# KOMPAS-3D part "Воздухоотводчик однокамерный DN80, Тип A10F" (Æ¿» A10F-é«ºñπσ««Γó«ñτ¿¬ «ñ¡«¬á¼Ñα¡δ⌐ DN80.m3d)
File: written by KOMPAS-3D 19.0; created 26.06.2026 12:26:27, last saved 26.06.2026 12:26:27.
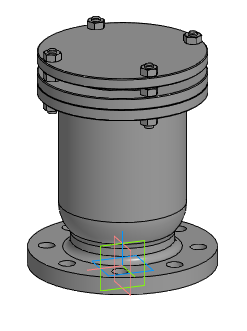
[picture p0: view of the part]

Document properties: Автор: Энергия; Полное имя файла: Z:\3.Личные\kachalov\001_3d для проектировщиков\х.х Тип A10F Воздухоотводчик однокамерный фланцевый\_step\Тип A10F-Воздухоотводчик однокамерный DN80.m3d

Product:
- Part/product: Воздухоотводчик однокамерный DN80  | designation Тип A10F

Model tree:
1. Операция без истории:1  (labels: Тип A10F; Воздухоотводчик однокамерный DN80)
